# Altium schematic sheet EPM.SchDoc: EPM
size B; Date: 12/18/2013; DrawnBy: David McCoy; Engineer: David McCoy (Cospan Design); DocumentNumber: 8; Revision: C; SheetNumber: 8; SheetTotal: 10
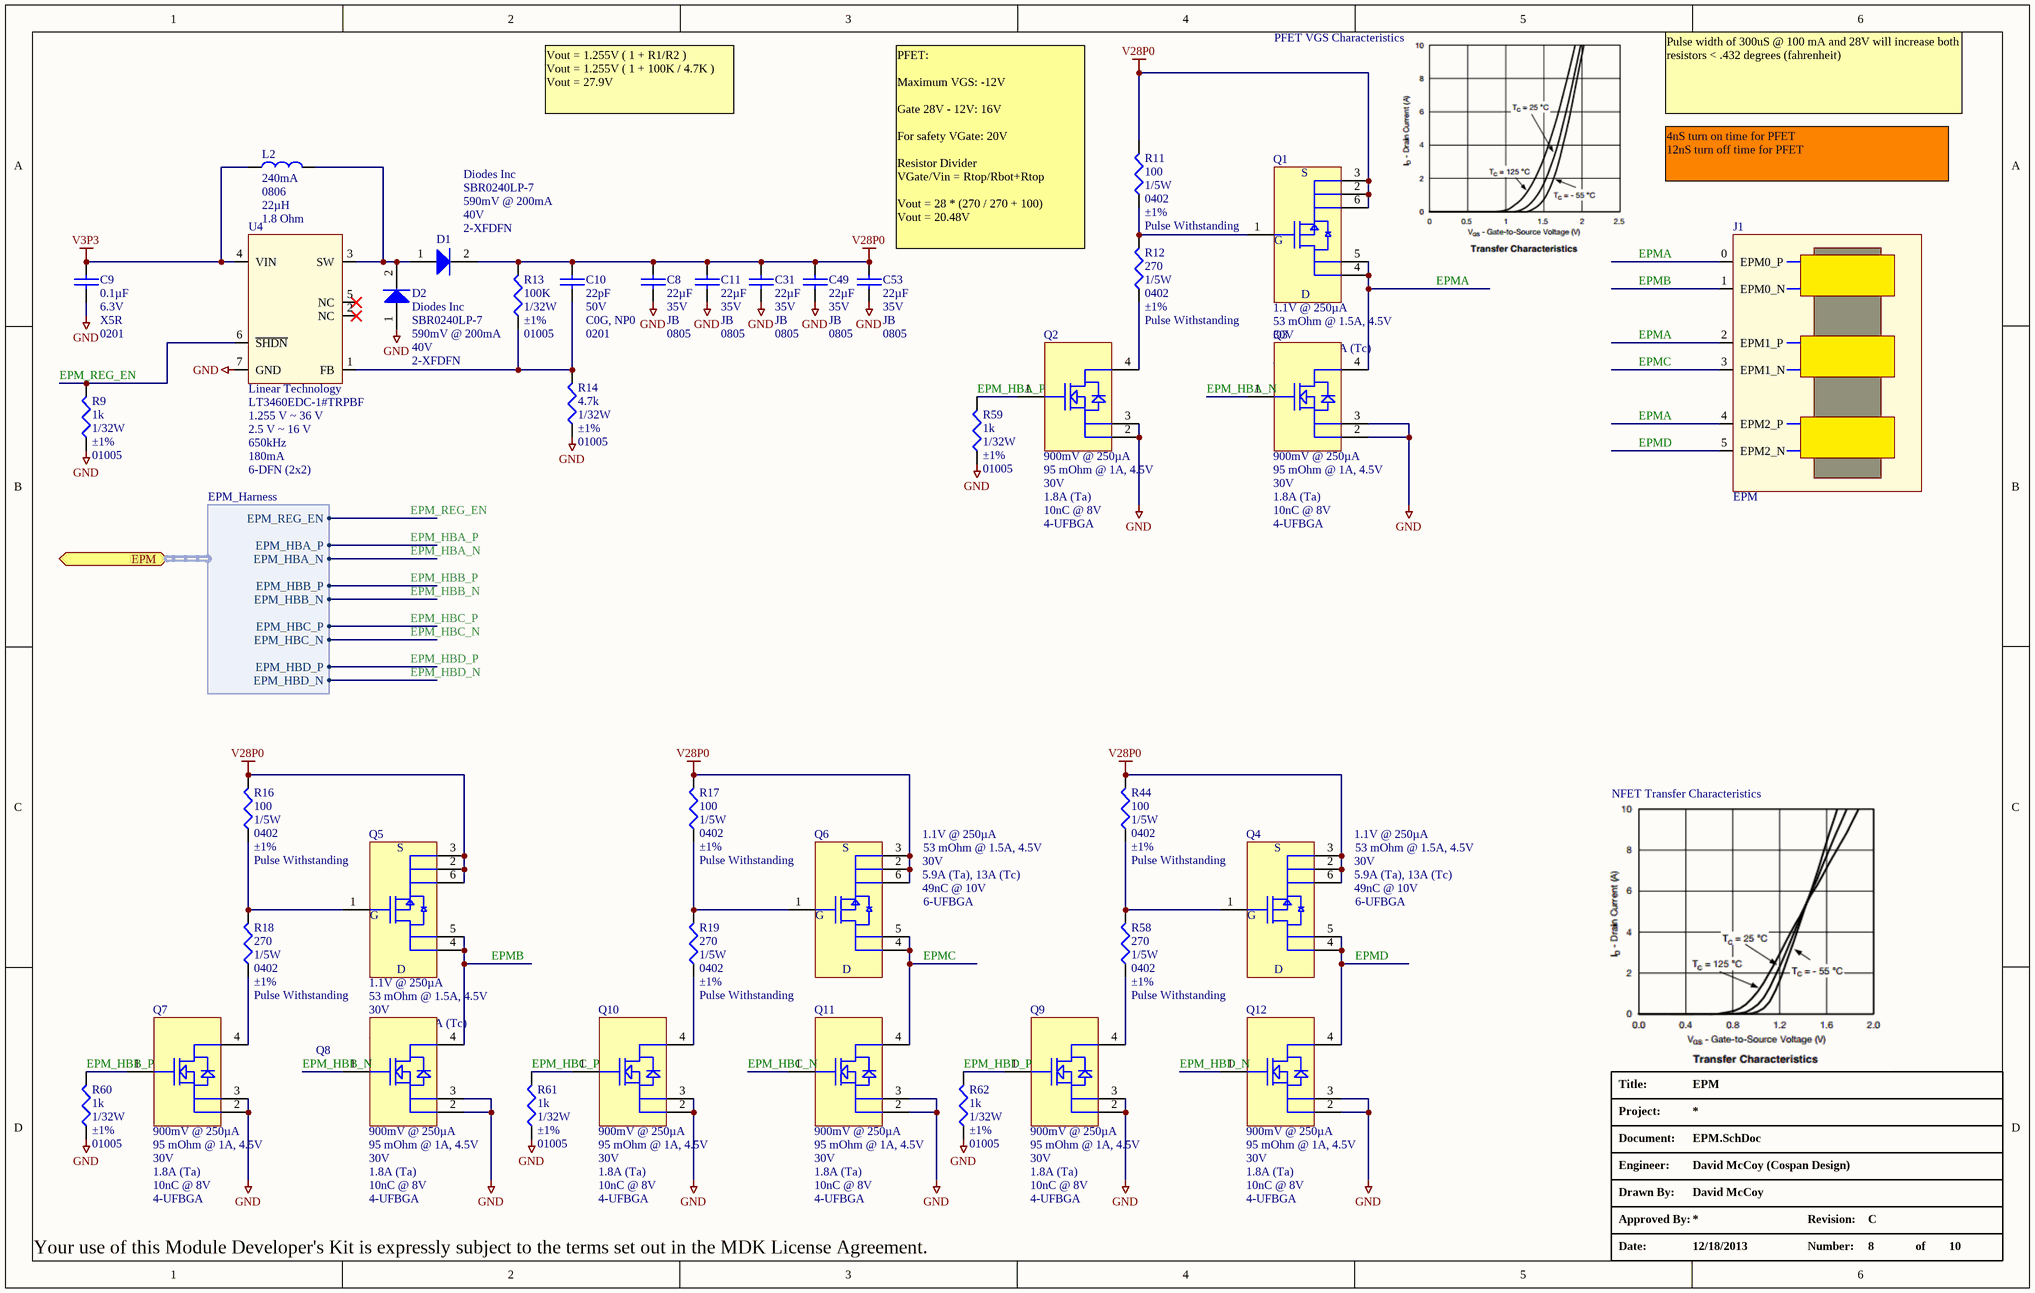
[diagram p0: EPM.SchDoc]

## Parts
C8  Voltage - Rated: 35V  Temperature Coefficient: JB  Package / Case: 0805  [C_ERA-0805]  (hidden comment: 22µF)
C9  Capacitance: 0.1µF  Voltage - Rated: 6.3V  Temperature Coefficient: X5R  Package / Case: 0201  [CAPC0201]  (hidden comment: 0.1UF)
C10  Capacitance: 22pF  Voltage - Rated: 50V  Temperature Coefficient: C0G, NP0  Package / Case: 0201  [CAPC0201]  (hidden comment: C_0201_22pF)
C11  Voltage - Rated: 35V  Temperature Coefficient: JB  Package / Case: 0805  [C_ERA-0805]  (hidden comment: 22µF)
C31  Voltage - Rated: 35V  Temperature Coefficient: JB  Package / Case: 0805  [C_ERA-0805]  (hidden comment: 22µF)
C49  Voltage - Rated: 35V  Temperature Coefficient: JB  Package / Case: 0805  [C_ERA-0805]  (hidden comment: 22µF)
C53  Voltage - Rated: 35V  Temperature Coefficient: JB  Package / Case: 0805  [C_ERA-0805]  (hidden comment: 22µF)
D1  Manufacturer: Diodes Inc  Voltage - Forward (Vf) (Max) @ If: 590mV @ 200mA  Voltage - DC Reverse (Vr) (Max): 40V  [2-XFDFN]  (hidden comment: SBR0240LP-7)
D2  Manufacturer: Diodes Inc  Voltage - Forward (Vf) (Max) @ If: 590mV @ 200mA  Voltage - DC Reverse (Vr) (Max): 40V  [2-XFDFN]  (hidden comment: SBR0240LP-7)
J1  EPM  [EPM_3X_CONNECTION]  (no BOM)
L2  Current: 240mA  Package / Case: 0806  Inductance: 22µH  DC Resistance (DCR): 1.8 Ohm  [L_0806]  (hidden comment: CBC2016T220K)
Q1  Vgs(th) (Max) @ Id: 1.1V @ 250µA  Rds On (Max) @ Id, Vgs: 53 mOhm @ 1.5A, 4.5V  Drain to Source Voltage (Vdss): 30V  Current - Continuous Drain (Id) @ 25° C: 5.9A (Ta), 13A (Tc)  Gate Charge (Qg) @ Vgs: 49nC @ 10V  Supplier Device Package: 6-UFBGA  [BGA6C50P3X2_145X96X59]  (hidden comment: SI8497DB-T2-E1)
Q2  Vgs(th) (Max) @ Id: 900mV @ 250µA  Rds On (Max) @ Id, Vgs: 95 mOhm @ 1A, 4.5V  Drain to Source Voltage (Vdss): 30V  Current - Continuous Drain (Id) @ 25° C: 1.8A (Ta)  Gate Charge (Qg) @ Vgs: 10nC @ 8V  Supplier Device Package: 4-UFBGA  [BGA4C40P2X2_80X80X40]  (hidden comment: SI8808DB-T2-E1)
Q3  Vgs(th) (Max) @ Id: 900mV @ 250µA  Rds On (Max) @ Id, Vgs: 95 mOhm @ 1A, 4.5V  Drain to Source Voltage (Vdss): 30V  Current - Continuous Drain (Id) @ 25° C: 1.8A (Ta)  Gate Charge (Qg) @ Vgs: 10nC @ 8V  Supplier Device Package: 4-UFBGA  [BGA4C40P2X2_80X80X40]  (hidden comment: SI8808DB-T2-E1)
Q4  Vgs(th) (Max) @ Id: 1.1V @ 250µA  Rds On (Max) @ Id, Vgs: 53 mOhm @ 1.5A, 4.5V  Drain to Source Voltage (Vdss): 30V  Current - Continuous Drain (Id) @ 25° C: 5.9A (Ta), 13A (Tc)  Gate Charge (Qg) @ Vgs: 49nC @ 10V  Supplier Device Package: 6-UFBGA  [BGA6C50P3X2_145X96X59]  (hidden comment: SI8497DB-T2-E1)
Q5  Vgs(th) (Max) @ Id: 1.1V @ 250µA  Rds On (Max) @ Id, Vgs: 53 mOhm @ 1.5A, 4.5V  Drain to Source Voltage (Vdss): 30V  Current - Continuous Drain (Id) @ 25° C: 5.9A (Ta), 13A (Tc)  Gate Charge (Qg) @ Vgs: 49nC @ 10V  Supplier Device Package: 6-UFBGA  [BGA6C50P3X2_145X96X59]  (hidden comment: SI8497DB-T2-E1)
Q6  Vgs(th) (Max) @ Id: 1.1V @ 250µA  Rds On (Max) @ Id, Vgs: 53 mOhm @ 1.5A, 4.5V  Drain to Source Voltage (Vdss): 30V  Current - Continuous Drain (Id) @ 25° C: 5.9A (Ta), 13A (Tc)  Gate Charge (Qg) @ Vgs: 49nC @ 10V  Supplier Device Package: 6-UFBGA  [BGA6C50P3X2_145X96X59]  (hidden comment: SI8497DB-T2-E1)
Q7  Vgs(th) (Max) @ Id: 900mV @ 250µA  Rds On (Max) @ Id, Vgs: 95 mOhm @ 1A, 4.5V  Drain to Source Voltage (Vdss): 30V  Current - Continuous Drain (Id) @ 25° C: 1.8A (Ta)  Gate Charge (Qg) @ Vgs: 10nC @ 8V  Supplier Device Package: 4-UFBGA  [BGA4C40P2X2_80X80X40]  (hidden comment: SI8808DB-T2-E1)
Q8  Vgs(th) (Max) @ Id: 900mV @ 250µA  Rds On (Max) @ Id, Vgs: 95 mOhm @ 1A, 4.5V  Drain to Source Voltage (Vdss): 30V  Current - Continuous Drain (Id) @ 25° C: 1.8A (Ta)  Gate Charge (Qg) @ Vgs: 10nC @ 8V  Supplier Device Package: 4-UFBGA  [BGA4C40P2X2_80X80X40]  (hidden comment: SI8808DB-T2-E1)
Q9  Vgs(th) (Max) @ Id: 900mV @ 250µA  Rds On (Max) @ Id, Vgs: 95 mOhm @ 1A, 4.5V  Drain to Source Voltage (Vdss): 30V  Current - Continuous Drain (Id) @ 25° C: 1.8A (Ta)  Gate Charge (Qg) @ Vgs: 10nC @ 8V  Supplier Device Package: 4-UFBGA  [BGA4C40P2X2_80X80X40]  (hidden comment: SI8808DB-T2-E1)
Q10  Vgs(th) (Max) @ Id: 900mV @ 250µA  Rds On (Max) @ Id, Vgs: 95 mOhm @ 1A, 4.5V  Drain to Source Voltage (Vdss): 30V  Current - Continuous Drain (Id) @ 25° C: 1.8A (Ta)  Gate Charge (Qg) @ Vgs: 10nC @ 8V  Supplier Device Package: 4-UFBGA  [BGA4C40P2X2_80X80X40]  (hidden comment: SI8808DB-T2-E1)
Q11  Vgs(th) (Max) @ Id: 900mV @ 250µA  Rds On (Max) @ Id, Vgs: 95 mOhm @ 1A, 4.5V  Drain to Source Voltage (Vdss): 30V  Current - Continuous Drain (Id) @ 25° C: 1.8A (Ta)  Gate Charge (Qg) @ Vgs: 10nC @ 8V  Supplier Device Package: 4-UFBGA  [BGA4C40P2X2_80X80X40]  (hidden comment: SI8808DB-T2-E1)
Q12  Vgs(th) (Max) @ Id: 900mV @ 250µA  Rds On (Max) @ Id, Vgs: 95 mOhm @ 1A, 4.5V  Drain to Source Voltage (Vdss): 30V  Current - Continuous Drain (Id) @ 25° C: 1.8A (Ta)  Gate Charge (Qg) @ Vgs: 10nC @ 8V  Supplier Device Package: 4-UFBGA  [BGA4C40P2X2_80X80X40]  (hidden comment: SI8808DB-T2-E1)
R9  Power (Watts): 1/32W  Tolerance: ±1%  Case: 01005  [R_01005]  (hidden comment: 1k)
R11  Power (Watts): 1/5W  Case: 0402  Tolerance: ±1%  [R_0402]  (hidden comment: 100)
R12  Power (Watts): 1/5W  Case: 0402  Tolerance: ±1%  [R_0402]  (hidden comment: 270)
R13  Resistance In Ohms: 100K  Power (Watts): 1/32W  Tolerance: ±1%  Case: 01005  [R_01005]  (hidden comment: 10K)
R14  Power (Watts): 1/32W  Tolerance: ±1%  Case: 01005  [R_01005]  (hidden comment: 4.7k)
R16  Power (Watts): 1/5W  Case: 0402  Tolerance: ±1%  [R_0402]  (hidden comment: 100)
R17  Power (Watts): 1/5W  Case: 0402  Tolerance: ±1%  [R_0402]  (hidden comment: 100)
R18  Power (Watts): 1/5W  Case: 0402  Tolerance: ±1%  [R_0402]  (hidden comment: 270)
R19  Power (Watts): 1/5W  Case: 0402  Tolerance: ±1%  [R_0402]  (hidden comment: 270)
R44  Power (Watts): 1/5W  Case: 0402  Tolerance: ±1%  [R_0402]  (hidden comment: 100)
R58  Power (Watts): 1/5W  Case: 0402  Tolerance: ±1%  [R_0402]  (hidden comment: 270)
R59  Power (Watts): 1/32W  Tolerance: ±1%  Case: 01005  [R_01005]  (hidden comment: 1k)
R60  Power (Watts): 1/32W  Tolerance: ±1%  Case: 01005  [R_01005]  (hidden comment: 1k)
R61  Power (Watts): 1/32W  Tolerance: ±1%  Case: 01005  [R_01005]  (hidden comment: 1k)
R62  Power (Watts): 1/32W  Tolerance: ±1%  Case: 01005  [R_01005]  (hidden comment: 1k)
U4  Manufacturer: Linear Technology  Manufacturer Part Number: LT3460EDC-1#TRPBF  Voltage - Output: 1.255 V ~ 36 V  Voltage - Input: 2.5 V ~ 16 V  Frequency - Switching: 650kHz  Current - Output: 180mA  Supplier Device Package: 6-DFN (2x2)  [DFN6]  (hidden comment: U_LT3460EDC-1)

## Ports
EPM (harness EPM_Harness)

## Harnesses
EPM_Harness: EPM_REG_EN, EPM_HBA_P, EPM_HBA_N, EPM_HBB_P, EPM_HBB_N, EPM_HBC_P, EPM_HBC_N, EPM_HBD_P, EPM_HBD_N

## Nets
GND: C8.1 C9.1 C11.1 C31.1 C49.1 C53.1 D2.1(A) Q2.2(S2) Q2.3(S) Q3.2(S2) Q3.3(S) Q7.2(S2) Q7.3(S) Q8.2(S2) Q8.3(S) Q9.2(S2) Q9.3(S) Q10.2(S2) Q10.3(S) Q11.2(S2) Q11.3(S) Q12.2(S2) Q12.3(S) R9.2 R14.2 R59.2 R60.2 R61.2 R62.2 U4.7(GND)
V3P3: C9.2 L2.1 U4.4(VIN)
V28P0: C8.2 C10.2 C11.2 C31.2 C49.2 C53.2 D1.2(K) Q1.2(S2) Q1.3(S) Q1.6(S3) Q4.2(S2) Q4.3(S) Q4.6(S3) Q5.2(S2) Q5.3(S) Q5.6(S3) Q6.2(S2) Q6.3(S) Q6.6(S3) R11.1 R13.1 R16.1 R17.1 R44.1
EPM_HBA_N: Q3.1(G) ; port EPM.EPM_HBA_N
EPM_HBA_P: Q2.1(G) R59.1 ; port EPM.EPM_HBA_P
EPM_HBB_N: Q8.1(G) ; port EPM.EPM_HBB_N
EPM_HBB_P: Q7.1(G) R60.1 ; port EPM.EPM_HBB_P
EPM_HBC_N: Q11.1(G) ; port EPM.EPM_HBC_N
EPM_HBC_P: Q10.1(G) R61.1 ; port EPM.EPM_HBC_P
EPM_HBD_N: Q12.1(G) ; port EPM.EPM_HBD_N
EPM_HBD_P: Q9.1(G) R62.1 ; port EPM.EPM_HBD_P
EPM_REG_EN: R9.1 U4.6(~{SHDN}) ; port EPM.EPM_REG_EN
EPMA: J1.0(EPM0_P) J1.2(EPM1_P) J1.4(EPM2_P) Q1.4(D1) Q1.5(D2) Q3.4(D)
EPMB: J1.1(EPM0_N) Q5.4(D1) Q5.5(D2) Q8.4(D)
EPMC: J1.3(EPM1_N) Q6.4(D1) Q6.5(D2) Q11.4(D)
EPMD: J1.5(EPM2_N) Q4.4(D1) Q4.5(D2) Q12.4(D)
NetC10_1: C10.1 R13.2 R14.1 U4.1(FB)
NetD1_1: D1.1(A) D2.2(K) L2.2 U4.3(SW)
NetQ1_1: Q1.1(G) R11.2 R12.1
NetQ2_4: Q2.4(D) R12.2
NetQ4_1: Q4.1(G) R44.2 R58.1
NetQ5_1: Q5.1(G) R16.2 R18.1
NetQ6_1: Q6.1(G) R17.2 R19.1
NetQ7_4: Q7.4(D) R18.2
NetQ9_4: Q9.4(D) R58.2
NetQ10_4: Q10.4(D) R19.2

Not connected (* = marked no-connect by the designer): U4 2(NC)* 5(NC)*

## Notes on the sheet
- PFET VGS Characteristics
- Vout = 1.255V ( 1 + R1/R2 )
  Vout = 1.255V ( 1 + 100K / 4.7K )
  Vout = 27.9V
- Pulse width of 300uS @ 100 mA and 28V will increase both resistors < .432 degrees (fahrenheit)
- 4nS turn on time for PFET
  12nS turn off time for PFET
- PFET:
  Maximum VGS: -12V
  Gate 28V - 12V: 16V
  For safety VGate: 20V
  Resistor Divider
  VGate/Vin = Rtop/Rbot+Rtop
  Vout = 28 * (270 / 270 + 100)
  Vout = 20.48V
- NFET Transfer Characteristics

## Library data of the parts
C8 C11 C31 C49 C53 = C_0805_22µF_35V: CAP CER 22UF 35V 20% JB 0805; Manufacturer: TDK Corporation; Manufacturer Part Number: C2012JB1V226M125AC
C9 = C_0201_0.1UF: CAP CER 0.1UF 6.3V 10% X5R 0201; Manufacturer: TDK Corporation; Manufacturer Part Number: C0603X5R0J104M; Tolerance: ±20%
C10 = C_0201_22pF: CAP CER 22PF 50V 5% NP0 0201; Manufacturer: TDK Corporation; Manufacturer Part Number: C0603C0G1H220J030BA
D1 D2 = D_SBR0240LP-7: DIODE SUP BARRIER 40V 0.25A 2DFN; Diode Type: Super Barrier; Current - Average Rectified (Io): 250mA; Speed: Fast Recovery =< 500ns, > 200mA (Io); Current - Reverse Leakage @ Vr: 10µA @ 40V; Thermal Resistance: 270°C/W Ja
J1 = J_EPM_3_PAD
L2 = L_0806_22uH: INDUCTOR 22UH 10% 0806 SMD; Manufacturer: Taiyo Yuden; Type: Wirewound; Current - Saturation: 250mA; Shielding: Unshielded; Frequency - Self Resonant: 16MHz; Frequency - Test: 2.52MHz
Q1 Q4-Q6 = Q_PFET_BGA_30V: MOSFET P-CH D-S 30V MICROFOOT; Manufacturer: Vishay Siliconix; FET Type: MOSFET P-Channel, Metal Oxide; FET Feature: Logic Level Gate, 2.5V Drive; Input Capacitance (Ciss) @ Vds: 1320pF @ 15V; Power - Max: 13W
Q2 Q3 Q7-Q12 = Q_NFET_BGA_30V: MOSFET N-CH D-S 30V MICROFOOT; Manufacturer: Vishay Siliconix; FET Type: MOSFET N-Channel, Metal Oxide; FET Feature: Logic Level Gate, 1.5V Drive; Input Capacitance (Ciss) @ Vds: 330pF @ 15V
R9 R59-R62 = R_01005_1k: RES 1K OHM 1/32W 1% 01005 SM; Manufacturer: Panasonic Electronic Components; Manufacturer Part Number: ERJ-XGNF1001Y; Temperature Coefficient: ±200ppm/°C
R11 R16 R17 R44 = R_0402_100_5%_PW: RES 100 OHM 1/5W 5% 0402 SMD; Manufacturer: Rohm Semiconductor; Manufacturer Part Number: ESR01MZPJ101; Temperature Coefficient: ±200ppm/°C
R12 R18 R19 R58 = R_0402_270_5%_PW: RES 270 OHM 1/5W 5% 0402 SMD; Manufacturer: Rohm Semiconductor; Manufacturer Part Number: ESR01MZPJ271; Temperature Coefficient: ±200ppm/°C
R13 = R_01005_100K: RES 100K OHM 1/32W 1% 01005 SMD; Manufacturer: Yageo; Manufacturer Part Number: RC0100FR-07100KL; Temperature Coefficient: ±250ppm/°C
R14 = R_01005_4.7k: RES 4.7K OHM 1/32W 1% 01005 SMD; Manufacturer: Yageo; Manufacturer Part Number: RC0100FR-074K7L; Temperature Coefficient: ±250ppm/°C
U4 = U_LTC3460-1: IC REG BOOST ADJ 0.18A 6DFN; Output Type: Adjustable; Number of Outputs: 1; PWM Type: Current Mode; Synchronous Rectifier: No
